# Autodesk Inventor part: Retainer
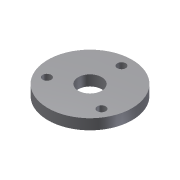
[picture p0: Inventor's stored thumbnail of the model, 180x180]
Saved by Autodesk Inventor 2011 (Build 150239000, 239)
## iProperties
Created: 2009-04
Part Number: Retainer
Document SubType Name: Modeling
Designer: Sham
Density: 1 g/cm^3
Author: Sham
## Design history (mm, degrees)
sketch "Sketch1"
  geometry: C1 r 100 at (0, 0); C2 r 28 at (0, 0)
  constraints: 2 centre point, 1 coincident
  dimensions: "d0" = 200 diameter of C1; "d1" = 56 diameter of C2
extrude "Extrusion2" new body sketch "Sketch1" distance "d10" = 25; taper "d11" = 0 deg
sketch "Sketch2"
  geometry: C1 r 28 at (0, 0) reference; 1 further point
  constraints: 1 vertical alignment
  dimensions: "d12" = 75 distance of C1.centre point (0, 75)
hole "Hole1" sketch "Sketch2" at (0, 75) diameter "d13" = 20.3; stored, may be unused: countersink angle "d17" = 90 deg, drill point angle "d19" = 118 deg; dims "d14" = 6, "d15" = 4, "d16" = 2, "d18" = 8
pattern_circular "Circular Pattern1" dims angle "d21" = 360 deg
body "Solid2"
